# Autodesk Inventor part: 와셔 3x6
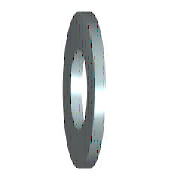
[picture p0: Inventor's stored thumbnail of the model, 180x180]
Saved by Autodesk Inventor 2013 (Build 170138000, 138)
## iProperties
IsCustomPart: 0
Created: 2012-02
Part Number: 와셔 3x6
Material: 강철, 연강
Description: 평면 와셔
Document SubType Name: Modeling
Standard: KS B 1326
Designer: mduedu
Standards Organization: KS
Language: ko-KR
Size Designation: 3x6
Categories: <MemberInstance><Categories><Category DisplayName="조임쇠" InternalName="e4da775c-781d-43d5-af7c-5136215cf5a6" Mnemonic="FSTN"><Category DisplayName="와셔" InternalN
Density: 7.86 g/cm^3
Mass: 0.0795112 g
Surface Area: 0.54915 cm^2
Volume: 0.0101159 cm^3
Author: mduedu
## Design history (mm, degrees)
sketch "스케치"
  geometry: C1 r 3 at (0, 0); C2 r 1.6 at (0, 0); 1 further point
  constraints: 2 centre point, 2 coincident
  dimensions: "d0" = 3.2 diameter of C2 (= SD1); "d1" = 6 diameter of C1 (= SD2)
extrude "본체" new body sketch "스케치" distance "d2" = 0.5 (= SD); taper "d3" = 0 deg
workaxis "Work Axis1"
workplane "Work Plane1"
body "Solid1"
other parameters: "SD1" = 3.2 [user parameter; used in 1 equation term], "SD2" = 6 [user parameter; used in 1 equation term], "SD" = 0.5 [user parameter; used in 1 equation term], "d4" = 0, "d5" = 0, "d6" = 0, "d7" = 0, "NND" = 3 [user parameter]
